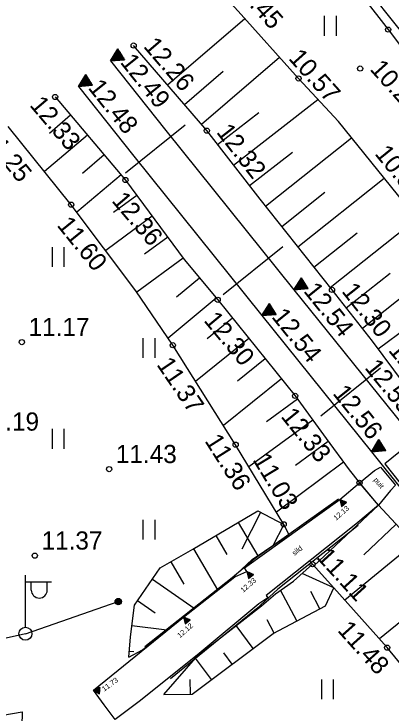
# Model space of a CAD drawing. Extents: x 554198 to 554371, y 6593448 to 6593563.
# Drawn here: x 554282.11 to 554296.62, y 6593507.8 to 6593534.71 of the extents above; entities that cross this region are included whole.
import ezdxf

# ---------------------------------------------------------------- set-up
doc = ezdxf.new("R2010")
doc.units = 0
for name, color, linetype in [('AED', 7, 'Continuous'), ('HALJASTUS', 7, 'Continuous'), ('KORGUS-EH2000', 7, 'Continuous'), ('MPOHULIIN', 7, 'Continuous'), ('PIIR', 7, 'Continuous'), ('POST', 7, 'Continuous'), ('RAJATIS', 7, 'Continuous'), ('RAJATISEDET', 7, 'Continuous'), ('RDT', 7, 'Continuous'), ('RELJEEF', 7, 'Continuous'), ('TEE', 7, 'Continuous')]:
    doc.layers.add(name, color=color, linetype=linetype)

msp = doc.modelspace()

# ---------------------------------------------------------------- linework, layer by layer
at = {"layer": 'AED'}
for points in [[(554287.143, 6593510.367), (554290.509, 6593513.013), (554291.357, 6593513.735), (554294.594, 6593516.043)], [(554295.352, 6593515.022), (554292.265, 6593512.565), (554291.446, 6593511.81), (554288.136, 6593509.114)]]:
    msp.add_lwpolyline(points, dxfattribs=at)
at = {"layer": 'HALJASTUS'}
for p, q in [((554294.052, 6593534.637), (554294.052, 6593533.876)), ((554294.507, 6593534.637), (554294.507, 6593533.876)), ((554283.572, 6593525.738), (554283.572, 6593524.976)), ((554284.028, 6593525.738), (554284.028, 6593524.976)), ((554287.072, 6593522.238), (554287.072, 6593521.476)), ((554287.528, 6593522.238), (554287.528, 6593521.476)), ((554283.572, 6593518.738), (554283.572, 6593517.976)), ((554284.028, 6593518.738), (554284.028, 6593517.976)), ((554287.072, 6593515.238), (554287.072, 6593514.476)), ((554287.528, 6593515.238), (554287.528, 6593514.476)), ((554293.944, 6593509.092), (554293.944, 6593508.331)), ((554294.399, 6593509.092), (554294.399, 6593508.331))]:
    msp.add_line(p, q, dxfattribs=at)
at = {"layer": 'KORGUS-EH2000'}
for p, q in [((554285.824, 6593532.905), (554286.109, 6593533.37)), ((554286.04, 6593533.257), (554286.006, 6593532.92)), ((554286.07, 6593533.306), (554286.032, 6593532.922)), ((554286.1, 6593533.354), (554286.057, 6593532.925)), ((554286.124, 6593533.347), (554286.082, 6593532.927)), ((554286.146, 6593533.311), (554286.108, 6593532.929)), ((554286.368, 6593532.951), (554286.109, 6593533.37)), ((554286.167, 6593533.276), (554286.133, 6593532.931)), ((554286.189, 6593533.241), (554286.158, 6593532.933)), ((554285.89, 6593533.012), (554285.88, 6593532.91)), ((554285.92, 6593533.061), (554285.905, 6593532.912)), ((554285.95, 6593533.11), (554285.93, 6593532.914)), ((554285.98, 6593533.159), (554285.956, 6593532.916)), ((554286.01, 6593533.208), (554285.981, 6593532.918)), ((554286.21, 6593533.206), (554286.184, 6593532.935)), ((554286.232, 6593533.171), (554286.209, 6593532.937)), ((554286.254, 6593533.136), (554286.234, 6593532.939)), ((554286.275, 6593533.101), (554286.26, 6593532.942)), ((554286.297, 6593533.066), (554286.285, 6593532.944)), ((554286.319, 6593533.03), (554286.31, 6593532.946)), ((554286.34, 6593532.995), (554286.336, 6593532.948)), ((554285.824, 6593532.905), (554286.368, 6593532.951)), ((554285.83, 6593532.915), (554285.829, 6593532.905)), ((554285.86, 6593532.963), (554285.854, 6593532.908)), ((554286.362, 6593532.96), (554286.361, 6593532.95)), ((554284.588, 6593531.92), (554284.873, 6593532.385)), ((554284.744, 6593532.174), (554284.72, 6593531.931)), ((554284.774, 6593532.223), (554284.745, 6593531.933)), ((554284.804, 6593532.272), (554284.77, 6593531.935)), ((554284.834, 6593532.321), (554284.796, 6593531.937)), ((554284.864, 6593532.369), (554284.821, 6593531.94)), ((554284.888, 6593532.362), (554284.846, 6593531.942)), ((554284.91, 6593532.326), (554284.872, 6593531.944)), ((554285.132, 6593531.966), (554284.873, 6593532.385)), ((554284.931, 6593532.291), (554284.897, 6593531.946)), ((554284.953, 6593532.256), (554284.922, 6593531.948)), ((554284.974, 6593532.221), (554284.948, 6593531.95)), ((554284.996, 6593532.186), (554284.973, 6593531.952)), ((554284.588, 6593531.92), (554285.132, 6593531.966)), ((554284.594, 6593531.93), (554284.593, 6593531.92)), ((554284.624, 6593531.978), (554284.618, 6593531.923)), ((554284.654, 6593532.027), (554284.644, 6593531.925)), ((554284.684, 6593532.076), (554284.669, 6593531.927)), ((554284.714, 6593532.125), (554284.694, 6593531.929)), ((554285.018, 6593532.151), (554284.998, 6593531.954)), ((554285.039, 6593532.116), (554285.024, 6593531.957)), ((554285.061, 6593532.081), (554285.049, 6593531.959)), ((554285.083, 6593532.045), (554285.074, 6593531.961)), ((554285.104, 6593532.01), (554285.1, 6593531.963)), ((554285.126, 6593531.975), (554285.125, 6593531.965)), ((554292.884, 6593524.093), (554293.169, 6593524.558)), ((554293.07, 6593524.396), (554293.041, 6593524.106)), ((554293.1, 6593524.445), (554293.066, 6593524.108)), ((554293.13, 6593524.494), (554293.092, 6593524.11)), ((554293.16, 6593524.542), (554293.117, 6593524.113)), ((554293.184, 6593524.535), (554293.142, 6593524.115)), ((554293.206, 6593524.499), (554293.168, 6593524.117)), ((554293.428, 6593524.139), (554293.169, 6593524.558)), ((554293.227, 6593524.464), (554293.193, 6593524.119)), ((554293.249, 6593524.429), (554293.218, 6593524.121)), ((554293.27, 6593524.394), (554293.244, 6593524.123)), ((554292.884, 6593524.093), (554293.428, 6593524.139)), ((554292.89, 6593524.103), (554292.889, 6593524.093)), ((554292.92, 6593524.151), (554292.914, 6593524.096)), ((554292.95, 6593524.2), (554292.94, 6593524.098)), ((554292.98, 6593524.249), (554292.965, 6593524.1)), ((554293.01, 6593524.298), (554292.99, 6593524.102)), ((554293.04, 6593524.347), (554293.016, 6593524.104)), ((554293.292, 6593524.359), (554293.269, 6593524.125)), ((554293.314, 6593524.324), (554293.294, 6593524.127)), ((554293.335, 6593524.289), (554293.32, 6593524.13)), ((554293.357, 6593524.254), (554293.345, 6593524.132)), ((554293.379, 6593524.218), (554293.37, 6593524.134)), ((554293.4, 6593524.183), (554293.396, 6593524.136)), ((554293.422, 6593524.148), (554293.421, 6593524.138)), ((554291.653, 6593523.103), (554291.938, 6593523.568)), ((554292.197, 6593523.149), (554291.938, 6593523.568)), ((554291.779, 6593523.308), (554291.759, 6593523.112)), ((554291.809, 6593523.357), (554291.785, 6593523.114)), ((554291.839, 6593523.406), (554291.81, 6593523.116)), ((554291.869, 6593523.455), (554291.835, 6593523.118)), ((554291.899, 6593523.504), (554291.861, 6593523.12)), ((554291.929, 6593523.552), (554291.886, 6593523.123)), ((554291.953, 6593523.545), (554291.911, 6593523.125)), ((554291.975, 6593523.509), (554291.937, 6593523.127)), ((554291.996, 6593523.474), (554291.962, 6593523.129)), ((554292.018, 6593523.439), (554291.987, 6593523.131)), ((554292.039, 6593523.404), (554292.013, 6593523.133)), ((554292.061, 6593523.369), (554292.038, 6593523.135)), ((554292.083, 6593523.334), (554292.063, 6593523.137)), ((554292.104, 6593523.299), (554292.089, 6593523.14)), ((554291.653, 6593523.103), (554292.197, 6593523.149)), ((554291.659, 6593523.113), (554291.658, 6593523.103)), ((554291.689, 6593523.161), (554291.683, 6593523.106)), ((554291.719, 6593523.21), (554291.709, 6593523.108)), ((554291.749, 6593523.259), (554291.734, 6593523.11)), ((554292.126, 6593523.264), (554292.114, 6593523.142)), ((554292.148, 6593523.228), (554292.139, 6593523.144)), ((554292.169, 6593523.193), (554292.165, 6593523.146)), ((554292.191, 6593523.158), (554292.19, 6593523.148)), ((554295.871, 6593517.862), (554296.156, 6593518.327)), ((554296.087, 6593518.214), (554296.053, 6593517.877)), ((554296.117, 6593518.263), (554296.079, 6593517.879)), ((554296.147, 6593518.311), (554296.104, 6593517.882)), ((554296.171, 6593518.304), (554296.129, 6593517.884)), ((554296.193, 6593518.268), (554296.155, 6593517.886)), ((554296.415, 6593517.908), (554296.156, 6593518.327)), ((554296.214, 6593518.233), (554296.18, 6593517.888)), ((554296.236, 6593518.198), (554296.205, 6593517.89)), ((554295.871, 6593517.862), (554296.415, 6593517.908)), ((554295.907, 6593517.92), (554295.901, 6593517.865)), ((554295.937, 6593517.969), (554295.927, 6593517.867)), ((554295.967, 6593518.018), (554295.952, 6593517.869)), ((554295.997, 6593518.067), (554295.977, 6593517.871)), ((554296.027, 6593518.116), (554296.003, 6593517.873)), ((554296.057, 6593518.165), (554296.028, 6593517.875)), ((554296.257, 6593518.163), (554296.231, 6593517.892)), ((554296.279, 6593518.128), (554296.256, 6593517.894)), ((554296.301, 6593518.093), (554296.281, 6593517.896)), ((554296.322, 6593518.058), (554296.307, 6593517.899)), ((554296.344, 6593518.023), (554296.332, 6593517.901)), ((554296.366, 6593517.987), (554296.357, 6593517.903)), ((554296.387, 6593517.952), (554296.383, 6593517.905)), ((554296.409, 6593517.917), (554296.408, 6593517.907)), ((554295.877, 6593517.872), (554295.876, 6593517.862))]:
    msp.add_line(p, q, dxfattribs=at)
for centre in [(554296.51, 6593534.11), (554286.714, 6593533.498), (554295.43, 6593532.61), (554293.06, 6593532.23), (554283.69, 6593531.517), (554289.53, 6593530.22), (554286.4, 6593528.32), (554284.31, 6593527.37), (554294.35, 6593524.09), (554289.95, 6593523.71), (554282.41, 6593522.08), (554288.22, 6593521.96), (554292.93, 6593520.01), (554290.64, 6593518.13), (554285.77, 6593517.19), (554295.41, 6593516.667), (554292.491, 6593515.065), (554282.91, 6593513.86), (554293.599, 6593513.53), (554296.47, 6593510.32)]:
    msp.add_circle(centre, 0.1, dxfattribs=at)
at = {"layer": 'MPOHULIIN'}
msp.add_lwpolyline([(554282.548, 6593510.856), (554248.452, 6593503.231)], dxfattribs=at)
at = {"layer": 'PIIR'}
msp.add_line((554289.426, 6593543.649), (554309.59, 6593518.04), dxfattribs=at)
at = {"layer": 'POST'}
for p, q in [((554282.548, 6593511.106), (554282.548, 6593513.106)), ((554282.548, 6593512.856), (554283.548, 6593512.856)), ((554282.775, 6593512.535), (554282.775, 6593512.856)), ((554283.387, 6593512.535), (554283.387, 6593512.856)), ((554282.548, 6593510.856), (554286.123, 6593512.089))]:
    msp.add_line(p, q, dxfattribs=at)
for centre, radius in [((554286.123, 6593512.089), 0.125), ((554286.123, 6593512.089), 0.117), ((554286.123, 6593512.089), 0.109), ((554286.123, 6593512.089), 0.102), ((554286.123, 6593512.089), 0.0938), ((554286.123, 6593512.089), 0.086), ((554286.123, 6593512.089), 0.0782), ((554286.123, 6593512.089), 0.0704), ((554286.123, 6593512.089), 0.0626), ((554286.123, 6593512.089), 0.0548), ((554286.123, 6593512.089), 0.047), ((554286.123, 6593512.089), 0.0392), ((554286.123, 6593512.089), 0.0314), ((554286.123, 6593512.089), 0.0236), ((554286.123, 6593512.089), 0.0158), ((554286.123, 6593512.089), 0.00798), ((554286.123, 6593512.089), 0.000186), ((554282.548, 6593510.856), 0.25)]:
    msp.add_circle(centre, radius, dxfattribs=at)
msp.add_arc((554283.081, 6593512.535), 0.306, 180, 0, dxfattribs=at)
at = {"layer": 'RAJATIS'}
for points in [[(554296.378, 6593517.399), (554296.971, 6593516.654), (554298.04, 6593517.497), (554297.458, 6593518.268)], [(554295.41, 6593516.667), (554295.987, 6593517.134), (554296.216, 6593517.272), (554296.795, 6593516.578), (554296.603, 6593516.372), (554296.134, 6593515.797)]]:
    msp.add_lwpolyline(points, close=True, dxfattribs=at)
msp.add_lwpolyline([(554285.582, 6593508.122), (554285.164, 6593508.682), (554288.636, 6593511.498), (554290.603, 6593513.04), (554291.071, 6593513.244), (554290.979, 6593513.389), (554294.649, 6593516.02), (554295.41, 6593516.667), (554296.041, 6593515.909), (554296.134, 6593515.797), (554295.267, 6593515.075), (554291.81, 6593512.332), (554291.874, 6593512.238), (554291.529, 6593512.003), (554289.23, 6593510.089), (554286.977, 6593508.284), (554286.003, 6593507.557), (554285.582, 6593508.122)], dxfattribs=at)
at = {"layer": 'RAJATISEDET'}
for p, q in [((554294.649, 6593516.02), (554294.901, 6593515.914)), ((554294.649, 6593516.02), (554294.713, 6593515.755)), ((554294.654, 6593516.018), (554294.65, 6593516.018)), ((554294.681, 6593516.007), (554294.653, 6593516.005)), ((554294.707, 6593515.996), (554294.656, 6593515.993)), ((554294.733, 6593515.984), (554294.658, 6593515.98)), ((554294.76, 6593515.973), (554294.661, 6593515.968)), ((554294.786, 6593515.962), (554294.664, 6593515.956)), ((554294.813, 6593515.951), (554294.667, 6593515.943)), ((554294.839, 6593515.94), (554294.67, 6593515.931)), ((554294.866, 6593515.929), (554294.673, 6593515.919)), ((554294.892, 6593515.918), (554294.676, 6593515.906)), ((554294.89, 6593515.905), (554294.679, 6593515.894)), ((554294.874, 6593515.892), (554294.682, 6593515.882)), ((554294.859, 6593515.879), (554294.685, 6593515.869)), ((554294.843, 6593515.865), (554294.688, 6593515.857)), ((554294.827, 6593515.852), (554294.691, 6593515.845)), ((554294.811, 6593515.838), (554294.694, 6593515.832)), ((554294.796, 6593515.825), (554294.697, 6593515.82)), ((554294.78, 6593515.812), (554294.7, 6593515.807)), ((554294.764, 6593515.798), (554294.703, 6593515.795)), ((554294.748, 6593515.785), (554294.706, 6593515.783)), ((554294.733, 6593515.772), (554294.709, 6593515.77)), ((554294.717, 6593515.758), (554294.712, 6593515.758)), ((554294.713, 6593515.755), (554294.901, 6593515.914)), ((554291.071, 6593513.244), (554291.323, 6593513.138)), ((554291.071, 6593513.244), (554291.135, 6593512.979)), ((554291.076, 6593513.242), (554291.072, 6593513.242)), ((554291.103, 6593513.231), (554291.075, 6593513.229)), ((554291.129, 6593513.22), (554291.078, 6593513.217)), ((554291.155, 6593513.208), (554291.08, 6593513.204)), ((554291.182, 6593513.197), (554291.083, 6593513.192)), ((554291.208, 6593513.186), (554291.086, 6593513.18)), ((554291.235, 6593513.175), (554291.089, 6593513.167)), ((554291.261, 6593513.164), (554291.092, 6593513.155)), ((554291.288, 6593513.153), (554291.095, 6593513.143)), ((554291.314, 6593513.142), (554291.098, 6593513.13)), ((554291.312, 6593513.129), (554291.101, 6593513.118)), ((554291.296, 6593513.116), (554291.104, 6593513.106)), ((554291.281, 6593513.103), (554291.107, 6593513.093)), ((554291.265, 6593513.089), (554291.11, 6593513.081)), ((554291.249, 6593513.076), (554291.113, 6593513.069)), ((554291.233, 6593513.062), (554291.116, 6593513.056)), ((554291.135, 6593512.979), (554291.323, 6593513.138)), ((554291.218, 6593513.049), (554291.119, 6593513.044)), ((554291.202, 6593513.036), (554291.122, 6593513.031)), ((554291.186, 6593513.022), (554291.125, 6593513.019)), ((554291.17, 6593513.009), (554291.128, 6593513.007)), ((554291.155, 6593512.996), (554291.131, 6593512.994)), ((554291.139, 6593512.982), (554291.134, 6593512.982)), ((554288.636, 6593511.498), (554288.888, 6593511.392)), ((554288.636, 6593511.498), (554288.7, 6593511.233)), ((554288.641, 6593511.496), (554288.637, 6593511.496)), ((554288.668, 6593511.485), (554288.64, 6593511.483)), ((554288.694, 6593511.474), (554288.643, 6593511.471)), ((554288.72, 6593511.462), (554288.645, 6593511.458)), ((554288.747, 6593511.451), (554288.648, 6593511.446)), ((554288.773, 6593511.44), (554288.651, 6593511.434)), ((554288.8, 6593511.429), (554288.654, 6593511.421)), ((554288.826, 6593511.418), (554288.657, 6593511.409)), ((554288.853, 6593511.407), (554288.66, 6593511.397)), ((554288.879, 6593511.396), (554288.663, 6593511.384)), ((554288.877, 6593511.383), (554288.666, 6593511.372)), ((554288.861, 6593511.37), (554288.669, 6593511.36)), ((554288.846, 6593511.357), (554288.672, 6593511.347)), ((554288.83, 6593511.343), (554288.675, 6593511.335)), ((554288.814, 6593511.33), (554288.678, 6593511.323)), ((554288.798, 6593511.316), (554288.681, 6593511.31)), ((554288.783, 6593511.303), (554288.684, 6593511.298)), ((554288.767, 6593511.29), (554288.687, 6593511.285)), ((554288.751, 6593511.276), (554288.69, 6593511.273)), ((554288.735, 6593511.263), (554288.693, 6593511.261)), ((554288.72, 6593511.25), (554288.696, 6593511.248)), ((554288.704, 6593511.236), (554288.699, 6593511.236)), ((554288.7, 6593511.233), (554288.888, 6593511.392)), ((554285.164, 6593508.682), (554285.414, 6593508.792)), ((554285.326, 6593508.754), (554285.232, 6593508.643)), ((554285.353, 6593508.765), (554285.243, 6593508.636)), ((554285.379, 6593508.777), (554285.254, 6593508.63)), ((554285.405, 6593508.789), (554285.265, 6593508.624)), ((554285.413, 6593508.778), (554285.276, 6593508.618)), ((554285.412, 6593508.758), (554285.287, 6593508.611)), ((554285.401, 6593508.546), (554285.414, 6593508.792)), ((554285.164, 6593508.682), (554285.401, 6593508.546)), ((554285.169, 6593508.684), (554285.166, 6593508.681)), ((554285.195, 6593508.696), (554285.177, 6593508.674)), ((554285.222, 6593508.707), (554285.188, 6593508.668)), ((554285.248, 6593508.719), (554285.199, 6593508.662)), ((554285.274, 6593508.731), (554285.21, 6593508.655)), ((554285.3, 6593508.742), (554285.221, 6593508.649)), ((554285.411, 6593508.737), (554285.298, 6593508.605)), ((554285.41, 6593508.717), (554285.31, 6593508.599)), ((554285.409, 6593508.696), (554285.321, 6593508.592)), ((554285.407, 6593508.675), (554285.332, 6593508.586)), ((554285.406, 6593508.655), (554285.343, 6593508.58)), ((554285.405, 6593508.634), (554285.354, 6593508.573)), ((554285.404, 6593508.614), (554285.365, 6593508.567)), ((554285.403, 6593508.593), (554285.376, 6593508.561)), ((554285.402, 6593508.572), (554285.387, 6593508.554)), ((554285.401, 6593508.552), (554285.398, 6593508.548))]:
    msp.add_line(p, q, dxfattribs=at)
at = {"layer": 'RDT'}
for p, q in [((554286.397, 6593528.592), (554288.697, 6593530.44)), ((554290.155, 6593523.914), (554292.455, 6593525.762)), ((554293.916, 6593519.239), (554296.214, 6593521.088))]:
    msp.add_line(p, q, dxfattribs=at)
for points in [[(554285.824, 6593532.905), (554287.956, 6593530.229), (554292.884, 6593524.093), (554297.103, 6593518.851), (554302.239, 6593512.436), (554306.663, 6593506.945), (554311.64, 6593500.773)], [(554284.588, 6593531.92), (554286.722, 6593529.242), (554291.653, 6593523.103), (554295.871, 6593517.862), (554301.007, 6593511.447), (554305.433, 6593505.953), (554310.41, 6593499.781)]]:
    msp.add_lwpolyline(points, dxfattribs=at)
at = {"layer": 'RELJEEF'}
for p, q in [((554288.017, 6593531.981), (554290.992, 6593534.537)), ((554289.321, 6593530.464), (554292.328, 6593533.047)), ((554288.669, 6593531.222), (554290.164, 6593532.507)), ((554290.56, 6593528.895), (554293.808, 6593531.42)), ((554289.946, 6593529.684), (554291.537, 6593530.921)), ((554284.288, 6593530.811), (554283.47, 6593530.117)), ((554284.935, 6593530.048), (554283.28, 6593528.645)), ((554291.79, 6593527.318), (554295.101, 6593529.943)), ((554285.582, 6593529.285), (554284.745, 6593528.576)), ((554291.174, 6593528.105), (554292.832, 6593529.394)), ((554286.228, 6593528.523), (554284.528, 6593527.081)), ((554293.033, 6593525.751), (554296.359, 6593528.389)), ((554286.836, 6593527.729), (554285.938, 6593527.065)), ((554292.412, 6593526.534), (554294.071, 6593527.85)), ((554287.431, 6593526.925), (554285.64, 6593525.602)), ((554294.276, 6593524.184), (554297.618, 6593526.835)), ((554293.654, 6593524.967), (554295.322, 6593526.289)), ((554288.025, 6593526.121), (554287.133, 6593525.462)), ((554288.619, 6593525.316), (554286.84, 6593524.002)), ((554295.517, 6593522.616), (554298.933, 6593525.32)), ((554294.897, 6593523.4), (554296.586, 6593524.738)), ((554289.255, 6593524.545), (554288.365, 6593523.805)), ((554289.895, 6593523.776), (554288.037, 6593522.231)), ((554296.129, 6593521.825), (554297.878, 6593523.121)), ((554290.523, 6593522.998), (554289.543, 6593522.209)), ((554291.15, 6593522.22), (554289.1, 6593520.568)), ((554291.778, 6593521.441), (554290.708, 6593520.579)), ((554292.405, 6593520.662), (554290.175, 6593518.866)), ((554293.026, 6593519.878), (554291.829, 6593519.01)), ((554293.613, 6593519.069), (554291.151, 6593517.283)), ((554294.201, 6593518.26), (554292.945, 6593517.328)), ((554294.797, 6593517.457), (554292.207, 6593515.535)), ((554296.134, 6593515.797), (554293.651, 6593513.472)), ((554291.602, 6593515.522), (554290.877, 6593514.113)), ((554290.736, 6593515.137), (554291.491, 6593513.853)), ((554292.491, 6593515.065), (554292.068, 6593514.243)), ((554296.818, 6593515.067), (554295.568, 6593513.897)), ((554289.874, 6593514.63), (554290.297, 6593513.91)), ((554297.463, 6593514.303), (554294.837, 6593512.146)), ((554289.012, 6593514.123), (554289.943, 6593512.541)), ((554288.146, 6593513.624), (554288.64, 6593512.766)), ((554294.416, 6593512.617), (554293.199, 6593513.177)), ((554287.437, 6593512.953), (554289.047, 6593511.839)), ((554293.001, 6593511.348), (554292.373, 6593512.533)), ((554298.733, 6593512.758), (554296.172, 6593510.654)), ((554293.885, 6593511.816), (554293.53, 6593512.486)), ((554286.868, 6593512.131), (554287.546, 6593511.661)), ((554292.117, 6593510.88), (554291.849, 6593511.386)), ((554286.648, 6593511.174), (554287.989, 6593511)), ((554291.312, 6593510.287), (554290.655, 6593511.167)), ((554286.548, 6593510.18), (554286.724, 6593510.166)), ((554290.511, 6593509.688), (554290.189, 6593510.119)), ((554289.71, 6593509.09), (554289.096, 6593509.912)), ((554288.896, 6593508.529), (554288.886, 6593509.093)), ((554287.896, 6593508.51), (554287.896, 6593508.528))]:
    msp.add_line(p, q, dxfattribs=at)
for points in [[(554293.578, 6593537.902), (554296.51, 6593534.11), (554301.76, 6593527.14), (554303.649, 6593524.88), (554304.275, 6593523.857)], [(554301.7, 6593521.67), (554301.107, 6593522.455), (554299.02, 6593525.22), (554297.63, 6593526.82), (554294.593, 6593530.57), (554293.06, 6593532.23), (554290.734, 6593534.825), (554290.021, 6593535.62)], [(554298.228, 6593518.857), (554297.959, 6593519.355), (554295.91, 6593522.12), (554294.35, 6593524.09), (554291.583, 6593527.579), (554289.53, 6593530.22), (554286.714, 6593533.498)], [(554283.69, 6593531.517), (554286.4, 6593528.32), (554288.656, 6593525.266), (554289.95, 6593523.71), (554292.93, 6593520.01), (554294.119, 6593518.371), (554295.011, 6593517.169), (554295.41, 6593516.667)], [(554292.718, 6593514.636), (554292.491, 6593515.065), (554290.64, 6593518.13), (554288.22, 6593521.96), (554286.802, 6593524.059), (554284.31, 6593527.37), (554281.881, 6593530.377)], [(554309.146, 6593499.81), (554306.76, 6593502.86), (554304.63, 6593505.35), (554302.161, 6593508.188), (554298.83, 6593512.64), (554296.962, 6593514.913), (554296.134, 6593515.797)], [(554286.53, 6593509.95), (554286.591, 6593510.738), (554286.75, 6593511.96), (554287.74, 6593513.39), (554288.99, 6593514.11), (554291.49, 6593515.58), (554292.491, 6593515.065)], [(554286.53, 6593509.95), (554287.06, 6593510.24), (554288.293, 6593511.248), (554290.44, 6593512.93), (554291.28, 6593513.71), (554292.7, 6593514.67), (554292.7, 6593514.67)], [(554307.25, 6593498.822), (554304.78, 6593501.39), (554302.37, 6593503.94), (554299.35, 6593506.815), (554296.47, 6593510.32), (554294.416, 6593512.617), (554293.599, 6593513.53), (554293.482, 6593513.659)], [(554287.88, 6593508.51), (554289.19, 6593510.02), (554291.63, 6593511.93), (554292.17, 6593512.39), (554292.863, 6593512.88), (554293.599, 6593513.53)], [(554287.88, 6593508.51), (554288.96, 6593508.53), (554292.08, 6593510.86), (554294.1, 6593511.93), (554294.416, 6593512.617)]]:
    msp.add_lwpolyline(points, dxfattribs=at)
at = {"layer": 'TEE'}
msp.add_lwpolyline([(554280.554, 6593507.491), (554280.84, 6593507.575), (554282.423, 6593507.849), (554282.4, 6593506.737), (554282.147, 6593506.366), (554281.493, 6593506.397), (554281.123, 6593506.423), (554281.051, 6593506.447), (554280.525, 6593507.42)], close=True, dxfattribs=at)

# ---------------------------------------------------------------- texts
at = {"layer": 'KORGUS-EH2000'}
for s, rotation, p in [(' 10.45 ', 311.8711, (554290.276, 6593536.005)), (' 12.26 ', 310.6646, (554286.891, 6593533.65)), (' 10.57 ', 311.8711, (554292.472, 6593533.181)), (' 12.49 ', 308.5447, (554286.006, 6593533.05)), (' 10.24 ', 311.8711, (554295.604, 6593532.766)), (' 12.48 ', 308.5501, (554284.77, 6593532.065)), (' 12.33 ', 310.2869, (554282.515, 6593531.39)), (' 11.25 ', 308.9306, (554280.671, 6593530.197)), (' 12.32 ', 307.86, (554289.714, 6593530.363)), (' 10.56 ', 309.0029, (554295.803, 6593529.527)), (' 12.36 ', 310.2869, (554285.675, 6593527.706)), (' 11.60 ', 308.9306, (554283.571, 6593526.773)), (' 12.54 ', 308.8287, (554293.066, 6593524.239)), (' 12.30 ', 308.3749, (554294.533, 6593524.235)), (' 12.54 ', 308.8274, (554291.835, 6593523.249)), (' 12.30 ', 309.7476, (554289.22, 6593523.103)), (' 12.25 ', 310.0098, (554296.323, 6593521.954)), (' 11.37 ', 304.0414, (554287.433, 6593521.428)), (' 12.55 ', 308.6816, (554295.419, 6593521.29)), (' 12.56 ', 308.6816, (554294.187, 6593520.301)), (' 12.33 ', 308.8482, (554292.19, 6593519.414)), (' 11.36 ', 302.2869, (554289.291, 6593518.496)), (' 11.03 ', 301.1284, (554291.144, 6593517.778)), (' 11.11 ', 312.2073, (554293.551, 6593513.973)), (' 11.48 ', 311.8034, (554294.356, 6593511.164))]:
    msp.add_text(s, height=0.7, rotation=rotation, dxfattribs=at).set_placement(p)
for s, p in [(' 11.17 ', (554282.41, 6593522.313)), (' 11.19 ', (554280.47, 6593518.673)), (' 11.43 ', (554285.77, 6593517.423)), (' 11.37 ', (554282.91, 6593514.093))]:
    msp.add_text(s, height=0.7, dxfattribs=at).set_placement(p)
at = {"layer": 'RAJATIS'}
for s, rotation, p in [('puit', 307.9626, (554295.94, 6593516.771)), ('sild', 37.3531, (554292.906, 6593513.85))]:
    msp.add_text(s, height=0.2, rotation=rotation, dxfattribs=at).set_placement(p)
at = {"layer": 'RAJATISEDET'}
for s, rotation, p in [('12.13', 40.8947, (554294.509, 6593515.201)), ('12.33', 40.8947, (554290.931, 6593512.425)), ('12.12', 40.8947, (554288.496, 6593510.679)), ('11.73', 36.0337, (554285.582, 6593508.62))]:
    msp.add_text(s, height=0.2, rotation=rotation, dxfattribs=at).set_placement(p)

doc.saveas('drawing.dxf')
